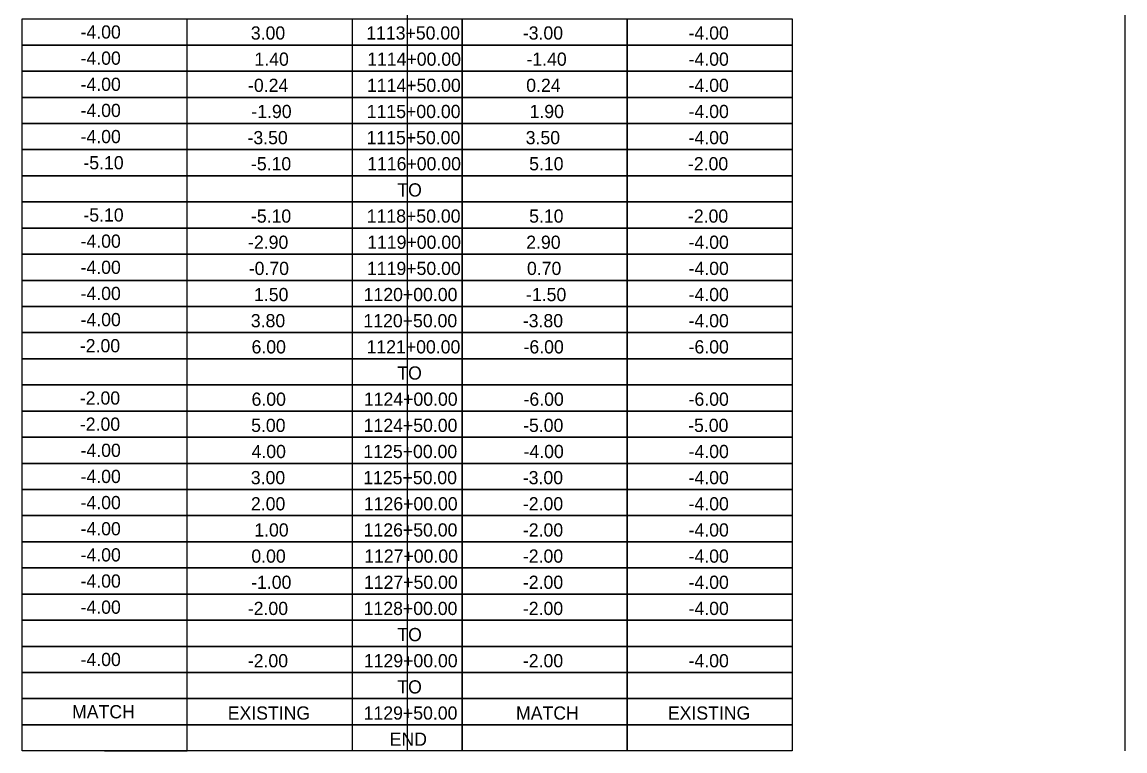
# Model space of a CAD drawing. Extents: x 1026502 to 1027102, y 781811 to 782040.
# Drawn here: x 1026950.62 to 1026990.71, y 781816.1 to 781842.59 of the extents above; entities that cross this region are included whole.
import ezdxf

# ---------------------------------------------------------------- set-up
doc = ezdxf.new("R2010")
doc.units = 0
doc.layers.add('BORDER', color=7, linetype='Continuous')
doc.layers.add('DIMENSIONS', color=7, linetype='Continuous')

msp = doc.modelspace()

# ---------------------------------------------------------------- linework, layer by layer
at = {"layer": 'BORDER'}
for p, q in [((1026964.619, 781922.543), (1026964.619, 781816.098)), ((1026990.71, 781922.543), (1026990.71, 781816.098)), ((1026953.619, 781841.759), (1026950.619, 781841.759)), ((1026953.619, 781841.759), (1026950.619, 781841.759)), ((1026953.619, 781841.759), (1026956.619, 781841.759)), ((1026953.619, 781840.808), (1026950.619, 781840.808)), ((1026953.619, 781840.808), (1026950.619, 781840.808)), ((1026953.619, 781840.808), (1026956.619, 781840.808)), ((1026953.619, 781839.858), (1026950.619, 781839.858)), ((1026953.619, 781839.858), (1026950.619, 781839.858)), ((1026953.619, 781839.858), (1026956.619, 781839.858)), ((1026953.619, 781838.907), (1026950.619, 781838.907)), ((1026953.619, 781838.907), (1026950.619, 781838.907)), ((1026953.619, 781838.907), (1026956.619, 781838.907)), ((1026953.619, 781837.957), (1026950.619, 781837.957)), ((1026953.619, 781837.957), (1026950.619, 781837.957)), ((1026953.619, 781837.957), (1026956.619, 781837.957)), ((1026953.619, 781837.007), (1026950.619, 781837.007)), ((1026953.619, 781837.007), (1026950.619, 781837.007)), ((1026953.619, 781837.007), (1026956.619, 781837.007)), ((1026953.619, 781836.056), (1026950.619, 781836.056)), ((1026953.619, 781836.056), (1026950.619, 781836.056)), ((1026953.619, 781836.056), (1026956.619, 781836.056)), ((1026953.619, 781835.106), (1026950.619, 781835.106)), ((1026953.619, 781835.106), (1026950.619, 781835.106)), ((1026953.619, 781835.106), (1026956.619, 781835.106)), ((1026953.619, 781834.155), (1026950.619, 781834.155)), ((1026953.619, 781834.155), (1026950.619, 781834.155)), ((1026953.619, 781834.155), (1026956.619, 781834.155)), ((1026953.619, 781833.205), (1026950.619, 781833.205)), ((1026953.619, 781833.205), (1026950.619, 781833.205)), ((1026953.619, 781833.205), (1026956.619, 781833.205)), ((1026953.619, 781832.255), (1026950.619, 781832.255)), ((1026953.619, 781832.255), (1026950.619, 781832.255)), ((1026953.619, 781832.255), (1026956.619, 781832.255)), ((1026953.619, 781831.304), (1026950.619, 781831.304)), ((1026953.619, 781831.304), (1026950.619, 781831.304)), ((1026953.619, 781831.304), (1026956.619, 781831.304)), ((1026953.619, 781830.354), (1026950.619, 781830.354)), ((1026953.619, 781830.354), (1026950.619, 781830.354)), ((1026953.619, 781830.354), (1026956.619, 781830.354)), ((1026953.619, 781829.403), (1026950.619, 781829.403)), ((1026953.619, 781829.403), (1026950.619, 781829.403)), ((1026953.619, 781829.403), (1026956.619, 781829.403)), ((1026953.619, 781828.453), (1026950.619, 781828.453)), ((1026953.619, 781828.453), (1026950.619, 781828.453)), ((1026953.619, 781828.453), (1026956.619, 781828.453)), ((1026953.619, 781827.503), (1026950.619, 781827.503)), ((1026953.619, 781827.503), (1026950.619, 781827.503)), ((1026953.619, 781827.503), (1026956.619, 781827.503)), ((1026953.619, 781826.552), (1026950.619, 781826.552)), ((1026953.619, 781826.552), (1026950.619, 781826.552)), ((1026953.619, 781826.552), (1026956.619, 781826.552)), ((1026953.619, 781825.602), (1026950.619, 781825.602)), ((1026953.619, 781825.602), (1026950.619, 781825.602)), ((1026953.619, 781825.602), (1026956.619, 781825.602)), ((1026953.619, 781824.651), (1026950.619, 781824.651)), ((1026953.619, 781824.651), (1026950.619, 781824.651)), ((1026953.619, 781824.651), (1026956.619, 781824.651)), ((1026953.619, 781823.701), (1026950.619, 781823.701)), ((1026953.619, 781823.701), (1026950.619, 781823.701)), ((1026953.619, 781823.701), (1026956.619, 781823.701)), ((1026953.619, 781822.751), (1026950.619, 781822.751)), ((1026953.619, 781822.751), (1026950.619, 781822.751)), ((1026953.619, 781822.751), (1026956.619, 781822.751)), ((1026953.619, 781821.8), (1026950.619, 781821.8)), ((1026953.619, 781821.8), (1026950.619, 781821.8)), ((1026953.619, 781821.8), (1026956.619, 781821.8)), ((1026953.619, 781820.85), (1026950.619, 781820.85)), ((1026953.619, 781820.85), (1026950.619, 781820.85)), ((1026953.619, 781820.85), (1026956.619, 781820.85)), ((1026953.619, 781819.899), (1026950.619, 781819.899)), ((1026953.619, 781819.899), (1026950.619, 781819.899)), ((1026953.619, 781819.899), (1026956.619, 781819.899)), ((1026953.619, 781818.949), (1026950.619, 781818.949)), ((1026953.619, 781818.949), (1026950.619, 781818.949)), ((1026953.619, 781818.949), (1026950.619, 781818.949)), ((1026953.619, 781818.949), (1026956.619, 781818.949)), ((1026953.619, 781818.949), (1026956.619, 781818.949)), ((1026953.619, 781817.999), (1026950.619, 781817.999)), ((1026953.619, 781817.999), (1026950.619, 781817.999)), ((1026953.619, 781817.999), (1026956.619, 781817.999)), ((1026953.619, 781817.048), (1026950.619, 781817.048)), ((1026953.619, 781817.048), (1026950.619, 781817.048)), ((1026953.619, 781817.048), (1026950.619, 781817.048)), ((1026953.619, 781817.048), (1026956.619, 781817.048)), ((1026953.619, 781817.048), (1026956.619, 781817.048)), ((1026953.619, 781816.098), (1026950.619, 781816.098)), ((1026953.619, 781816.098), (1026950.619, 781816.098)), ((1026953.619, 781816.098), (1026956.619, 781816.098))]:
    msp.add_line(p, q, dxfattribs=at)
for points in [[(1026950.619, 781842.709), (1026978.619, 781842.709), (1026978.619, 781841.759), (1026950.619, 781841.759)], [(1026950.619, 781841.759), (1026978.619, 781841.759), (1026978.619, 781840.808), (1026950.619, 781840.808)], [(1026950.619, 781840.808), (1026978.619, 781840.808), (1026978.619, 781839.858), (1026950.619, 781839.858)], [(1026950.619, 781839.858), (1026978.619, 781839.858), (1026978.619, 781838.907), (1026950.619, 781838.907)], [(1026950.619, 781838.907), (1026978.619, 781838.907), (1026978.619, 781837.957), (1026950.619, 781837.957)], [(1026950.619, 781837.957), (1026978.619, 781837.957), (1026978.619, 781837.007), (1026950.619, 781837.007)], [(1026950.619, 781837.007), (1026978.619, 781837.007), (1026978.619, 781836.056), (1026950.619, 781836.056)], [(1026950.619, 781836.056), (1026978.619, 781836.056), (1026978.619, 781835.106), (1026950.619, 781835.106)], [(1026950.619, 781835.106), (1026978.619, 781835.106), (1026978.619, 781834.155), (1026950.619, 781834.155)], [(1026950.619, 781834.155), (1026978.619, 781834.155), (1026978.619, 781833.205), (1026950.619, 781833.205)], [(1026950.619, 781833.205), (1026978.619, 781833.205), (1026978.619, 781832.255), (1026950.619, 781832.255)], [(1026950.619, 781832.255), (1026978.619, 781832.255), (1026978.619, 781831.304), (1026950.619, 781831.304)], [(1026950.619, 781831.304), (1026978.619, 781831.304), (1026978.619, 781830.354), (1026950.619, 781830.354)], [(1026950.619, 781830.354), (1026978.619, 781830.354), (1026978.619, 781829.403), (1026950.619, 781829.403)], [(1026950.619, 781829.403), (1026978.619, 781829.403), (1026978.619, 781828.453), (1026950.619, 781828.453)], [(1026950.619, 781828.453), (1026978.619, 781828.453), (1026978.619, 781827.503), (1026950.619, 781827.503)], [(1026950.619, 781827.503), (1026978.619, 781827.503), (1026978.619, 781826.552), (1026950.619, 781826.552)], [(1026950.619, 781826.552), (1026978.619, 781826.552), (1026978.619, 781825.602), (1026950.619, 781825.602)], [(1026950.619, 781825.602), (1026978.619, 781825.602), (1026978.619, 781824.651), (1026950.619, 781824.651)], [(1026950.619, 781824.651), (1026978.619, 781824.651), (1026978.619, 781823.701), (1026950.619, 781823.701)], [(1026950.619, 781823.701), (1026978.619, 781823.701), (1026978.619, 781822.751), (1026950.619, 781822.751)], [(1026950.619, 781822.751), (1026978.619, 781822.751), (1026978.619, 781821.8), (1026950.619, 781821.8)], [(1026950.619, 781821.8), (1026978.619, 781821.8), (1026978.619, 781820.85), (1026950.619, 781820.85)], [(1026950.619, 781820.85), (1026978.619, 781820.85), (1026978.619, 781819.899), (1026950.619, 781819.899)], [(1026950.619, 781819.899), (1026978.619, 781819.899), (1026978.619, 781818.949), (1026950.619, 781818.949)], [(1026950.619, 781818.949), (1026978.619, 781818.949), (1026978.619, 781817.999), (1026950.619, 781817.999)], [(1026950.619, 781817.999), (1026978.619, 781817.999), (1026978.619, 781817.048), (1026950.619, 781817.048)], [(1026950.619, 781817.048), (1026978.619, 781817.048), (1026978.619, 781816.098), (1026950.619, 781816.098)]]:
    msp.add_lwpolyline(points, close=True, dxfattribs=at)
for points in [[(1026962.619, 781842.709), (1026962.619, 781841.759), (1026956.619, 781841.759), (1026956.619, 781842.709)], [(1026966.619, 781842.709), (1026966.619, 781841.759), (1026962.619, 781841.759)], [(1026972.619, 781842.709), (1026972.619, 781841.759), (1026966.619, 781841.759), (1026966.619, 781842.709)], [(1026978.619, 781842.709), (1026978.619, 781841.759), (1026972.619, 781841.759), (1026972.619, 781842.709)], [(1026962.619, 781841.759), (1026962.619, 781840.808), (1026956.619, 781840.808), (1026956.619, 781841.759)], [(1026966.619, 781841.759), (1026966.619, 781840.808), (1026962.619, 781840.808)], [(1026972.619, 781841.759), (1026972.619, 781840.808), (1026966.619, 781840.808), (1026966.619, 781841.759)], [(1026978.619, 781841.759), (1026978.619, 781840.808), (1026972.619, 781840.808), (1026972.619, 781841.759)], [(1026962.619, 781840.808), (1026962.619, 781839.858), (1026956.619, 781839.858), (1026956.619, 781840.808)], [(1026966.619, 781840.808), (1026966.619, 781839.858), (1026962.619, 781839.858)], [(1026972.619, 781840.808), (1026972.619, 781839.858), (1026966.619, 781839.858), (1026966.619, 781840.808)], [(1026978.619, 781840.808), (1026978.619, 781839.858), (1026972.619, 781839.858), (1026972.619, 781840.808)], [(1026962.619, 781839.858), (1026962.619, 781838.907), (1026956.619, 781838.907), (1026956.619, 781839.858)], [(1026966.619, 781839.858), (1026966.619, 781838.907), (1026962.619, 781838.907)], [(1026972.619, 781839.858), (1026972.619, 781838.907), (1026966.619, 781838.907), (1026966.619, 781839.858)], [(1026978.619, 781839.858), (1026978.619, 781838.907), (1026972.619, 781838.907), (1026972.619, 781839.858)], [(1026962.619, 781838.907), (1026962.619, 781837.957), (1026956.619, 781837.957), (1026956.619, 781838.907)], [(1026966.619, 781838.907), (1026966.619, 781837.957), (1026962.619, 781837.957)], [(1026972.619, 781838.907), (1026972.619, 781837.957), (1026966.619, 781837.957), (1026966.619, 781838.907)], [(1026978.619, 781838.907), (1026978.619, 781837.957), (1026972.619, 781837.957), (1026972.619, 781838.907)], [(1026962.619, 781837.957), (1026962.619, 781837.007), (1026956.619, 781837.007), (1026956.619, 781837.957)], [(1026966.619, 781837.957), (1026966.619, 781837.007), (1026962.619, 781837.007)], [(1026972.619, 781837.957), (1026972.619, 781837.007), (1026966.619, 781837.007), (1026966.619, 781837.957)], [(1026978.619, 781837.957), (1026978.619, 781837.007), (1026972.619, 781837.007), (1026972.619, 781837.957)], [(1026962.619, 781837.007), (1026962.619, 781836.056), (1026956.619, 781836.056), (1026956.619, 781837.007)], [(1026966.619, 781837.007), (1026966.619, 781836.056), (1026962.619, 781836.056)], [(1026972.619, 781837.007), (1026972.619, 781836.056), (1026966.619, 781836.056), (1026966.619, 781837.007)], [(1026978.619, 781837.007), (1026978.619, 781836.056), (1026972.619, 781836.056), (1026972.619, 781837.007)], [(1026962.619, 781836.056), (1026962.619, 781835.106), (1026956.619, 781835.106), (1026956.619, 781836.056)], [(1026966.619, 781836.056), (1026966.619, 781835.106), (1026962.619, 781835.106)], [(1026972.619, 781836.056), (1026972.619, 781835.106), (1026966.619, 781835.106), (1026966.619, 781836.056)], [(1026978.619, 781836.056), (1026978.619, 781835.106), (1026972.619, 781835.106), (1026972.619, 781836.056)], [(1026962.619, 781835.106), (1026962.619, 781834.155), (1026956.619, 781834.155), (1026956.619, 781835.106)], [(1026966.619, 781835.106), (1026966.619, 781834.155), (1026962.619, 781834.155)], [(1026972.619, 781835.106), (1026972.619, 781834.155), (1026966.619, 781834.155), (1026966.619, 781835.106)], [(1026978.619, 781835.106), (1026978.619, 781834.155), (1026972.619, 781834.155), (1026972.619, 781835.106)], [(1026962.619, 781834.155), (1026962.619, 781833.205), (1026956.619, 781833.205), (1026956.619, 781834.155)], [(1026966.619, 781834.155), (1026966.619, 781833.205), (1026962.619, 781833.205)], [(1026972.619, 781834.155), (1026972.619, 781833.205), (1026966.619, 781833.205), (1026966.619, 781834.155)], [(1026978.619, 781834.155), (1026978.619, 781833.205), (1026972.619, 781833.205), (1026972.619, 781834.155)], [(1026962.619, 781833.205), (1026962.619, 781832.255), (1026956.619, 781832.255), (1026956.619, 781833.205)], [(1026966.619, 781833.205), (1026966.619, 781832.255), (1026962.619, 781832.255)], [(1026972.619, 781833.205), (1026972.619, 781832.255), (1026966.619, 781832.255), (1026966.619, 781833.205)], [(1026978.619, 781833.205), (1026978.619, 781832.255), (1026972.619, 781832.255), (1026972.619, 781833.205)], [(1026962.619, 781832.255), (1026962.619, 781831.304), (1026956.619, 781831.304), (1026956.619, 781832.255)], [(1026966.619, 781832.255), (1026966.619, 781831.304), (1026962.619, 781831.304)], [(1026972.619, 781832.255), (1026972.619, 781831.304), (1026966.619, 781831.304), (1026966.619, 781832.255)], [(1026978.619, 781832.255), (1026978.619, 781831.304), (1026972.619, 781831.304), (1026972.619, 781832.255)], [(1026962.619, 781831.304), (1026962.619, 781830.354), (1026956.619, 781830.354), (1026956.619, 781831.304)], [(1026966.619, 781831.304), (1026966.619, 781830.354), (1026962.619, 781830.354)], [(1026972.619, 781831.304), (1026972.619, 781830.354), (1026966.619, 781830.354), (1026966.619, 781831.304)], [(1026978.619, 781831.304), (1026978.619, 781830.354), (1026972.619, 781830.354), (1026972.619, 781831.304)], [(1026962.619, 781830.354), (1026962.619, 781829.403), (1026956.619, 781829.403), (1026956.619, 781830.354)], [(1026966.619, 781830.354), (1026966.619, 781829.403), (1026962.619, 781829.403)], [(1026972.619, 781830.354), (1026972.619, 781829.403), (1026966.619, 781829.403), (1026966.619, 781830.354)], [(1026978.619, 781830.354), (1026978.619, 781829.403), (1026972.619, 781829.403), (1026972.619, 781830.354)], [(1026962.619, 781829.403), (1026962.619, 781828.453), (1026956.619, 781828.453), (1026956.619, 781829.403)], [(1026966.619, 781829.403), (1026966.619, 781828.453), (1026962.619, 781828.453)], [(1026972.619, 781829.403), (1026972.619, 781828.453), (1026966.619, 781828.453), (1026966.619, 781829.403)], [(1026978.619, 781829.403), (1026978.619, 781828.453), (1026972.619, 781828.453), (1026972.619, 781829.403)], [(1026962.619, 781828.453), (1026962.619, 781827.503), (1026956.619, 781827.503), (1026956.619, 781828.453)], [(1026966.619, 781828.453), (1026966.619, 781827.503), (1026962.619, 781827.503)], [(1026972.619, 781828.453), (1026972.619, 781827.503), (1026966.619, 781827.503), (1026966.619, 781828.453)], [(1026978.619, 781828.453), (1026978.619, 781827.503), (1026972.619, 781827.503), (1026972.619, 781828.453)], [(1026962.619, 781827.503), (1026962.619, 781826.552), (1026956.619, 781826.552), (1026956.619, 781827.503)], [(1026966.619, 781827.503), (1026966.619, 781826.552), (1026962.619, 781826.552)], [(1026972.619, 781827.503), (1026972.619, 781826.552), (1026966.619, 781826.552), (1026966.619, 781827.503)], [(1026978.619, 781827.503), (1026978.619, 781826.552), (1026972.619, 781826.552), (1026972.619, 781827.503)], [(1026962.619, 781826.552), (1026962.619, 781825.602), (1026956.619, 781825.602), (1026956.619, 781826.552)], [(1026966.619, 781826.552), (1026966.619, 781825.602), (1026962.619, 781825.602)], [(1026972.619, 781826.552), (1026972.619, 781825.602), (1026966.619, 781825.602), (1026966.619, 781826.552)], [(1026978.619, 781826.552), (1026978.619, 781825.602), (1026972.619, 781825.602), (1026972.619, 781826.552)], [(1026962.619, 781825.602), (1026962.619, 781824.651), (1026956.619, 781824.651), (1026956.619, 781825.602)], [(1026966.619, 781825.602), (1026966.619, 781824.651), (1026962.619, 781824.651)], [(1026972.619, 781825.602), (1026972.619, 781824.651), (1026966.619, 781824.651), (1026966.619, 781825.602)], [(1026978.619, 781825.602), (1026978.619, 781824.651), (1026972.619, 781824.651), (1026972.619, 781825.602)], [(1026962.619, 781824.651), (1026962.619, 781823.701), (1026956.619, 781823.701), (1026956.619, 781824.651)], [(1026966.619, 781824.651), (1026966.619, 781823.701), (1026962.619, 781823.701)], [(1026972.619, 781824.651), (1026972.619, 781823.701), (1026966.619, 781823.701), (1026966.619, 781824.651)], [(1026978.619, 781824.651), (1026978.619, 781823.701), (1026972.619, 781823.701), (1026972.619, 781824.651)], [(1026962.619, 781823.701), (1026962.619, 781822.751), (1026956.619, 781822.751), (1026956.619, 781823.701)], [(1026966.619, 781823.701), (1026966.619, 781822.751), (1026962.619, 781822.751)], [(1026972.619, 781823.701), (1026972.619, 781822.751), (1026966.619, 781822.751), (1026966.619, 781823.701)], [(1026978.619, 781823.701), (1026978.619, 781822.751), (1026972.619, 781822.751), (1026972.619, 781823.701)], [(1026962.619, 781822.751), (1026962.619, 781821.8), (1026956.619, 781821.8), (1026956.619, 781822.751)], [(1026966.619, 781822.751), (1026966.619, 781821.8), (1026962.619, 781821.8)], [(1026972.619, 781822.751), (1026972.619, 781821.8), (1026966.619, 781821.8), (1026966.619, 781822.751)], [(1026978.619, 781822.751), (1026978.619, 781821.8), (1026972.619, 781821.8), (1026972.619, 781822.751)], [(1026962.619, 781821.8), (1026962.619, 781820.85), (1026956.619, 781820.85), (1026956.619, 781821.8)], [(1026966.619, 781821.8), (1026966.619, 781820.85), (1026962.619, 781820.85)], [(1026972.619, 781821.8), (1026972.619, 781820.85), (1026966.619, 781820.85), (1026966.619, 781821.8)], [(1026978.619, 781821.8), (1026978.619, 781820.85), (1026972.619, 781820.85), (1026972.619, 781821.8)], [(1026962.619, 781820.85), (1026962.619, 781819.899), (1026956.619, 781819.899), (1026956.619, 781820.85)], [(1026966.619, 781820.85), (1026966.619, 781819.899), (1026962.619, 781819.899)], [(1026972.619, 781820.85), (1026972.619, 781819.899), (1026966.619, 781819.899), (1026966.619, 781820.85)], [(1026978.619, 781820.85), (1026978.619, 781819.899), (1026972.619, 781819.899), (1026972.619, 781820.85)], [(1026962.619, 781819.899), (1026962.619, 781818.949), (1026956.619, 781818.949), (1026956.619, 781819.899)], [(1026966.619, 781819.899), (1026966.619, 781818.949), (1026962.619, 781818.949)], [(1026972.619, 781819.899), (1026972.619, 781818.949), (1026966.619, 781818.949), (1026966.619, 781819.899)], [(1026978.619, 781819.899), (1026978.619, 781818.949), (1026972.619, 781818.949), (1026972.619, 781819.899)], [(1026962.619, 781818.949), (1026962.619, 781817.999), (1026956.619, 781817.999), (1026956.619, 781818.949)], [(1026966.619, 781818.949), (1026966.619, 781817.999), (1026962.619, 781817.999)], [(1026972.619, 781818.949), (1026972.619, 781817.999), (1026966.619, 781817.999), (1026966.619, 781818.949)], [(1026978.619, 781818.949), (1026978.619, 781817.999), (1026972.619, 781817.999), (1026972.619, 781818.949)], [(1026962.619, 781817.999), (1026962.619, 781817.048), (1026956.619, 781817.048), (1026956.619, 781817.999)], [(1026966.619, 781817.999), (1026966.619, 781817.048), (1026962.619, 781817.048)], [(1026972.619, 781817.999), (1026972.619, 781817.048), (1026966.619, 781817.048), (1026966.619, 781817.999)], [(1026978.619, 781817.999), (1026978.619, 781817.048), (1026972.619, 781817.048), (1026972.619, 781817.999)], [(1026962.619, 781817.048), (1026962.619, 781816.098), (1026956.619, 781816.098), (1026956.619, 781817.048)], [(1026966.619, 781817.048), (1026966.619, 781816.098), (1026962.619, 781816.098)], [(1026972.619, 781817.048), (1026972.619, 781816.098), (1026966.619, 781816.098), (1026966.619, 781817.048)], [(1026978.619, 781817.048), (1026978.619, 781816.098), (1026972.619, 781816.098), (1026972.619, 781817.048)]]:
    msp.add_lwpolyline(points, dxfattribs=at)

# ---------------------------------------------------------------- texts
at = {"layer": 'DIMENSIONS'}
for s, p in [('-4.00', (1026952.745, 781841.994)), ('3.00', (1026958.935, 781841.958)), ('1113+50.00', (1026963.13, 781841.958)), ('-3.00', (1026968.822, 781841.958)), ('-4.00', (1026974.848, 781841.958)), ('-4.00', (1026952.745, 781841.043)), ('1.40', (1026959.067, 781841.007)), ('1114+00.00', (1026963.164, 781841.007)), ('-1.40', (1026968.954, 781841.007)), ('-4.00', (1026974.848, 781841.007)), ('-4.00', (1026952.745, 781840.093)), ('-0.24', (1026958.833, 781840.056)), ('1114+50.00', (1026963.157, 781840.056)), ('0.24', (1026968.946, 781840.056)), ('-4.00', (1026974.848, 781840.056)), ('-4.00', (1026952.745, 781839.143)), ('-1.90', (1026958.954, 781839.105)), ('1115+00.00', (1026963.149, 781839.105)), ('1.90', (1026969.067, 781839.105)), ('-4.00', (1026974.848, 781839.105)), ('-4.00', (1026952.745, 781838.192)), ('-3.50', (1026958.814, 781838.154)), ('1115+50.00', (1026963.142, 781838.154)), ('3.50', (1026968.927, 781838.154)), ('-4.00', (1026974.848, 781838.154)), ('-5.10', (1026952.848, 781837.242)), ('-5.10', (1026958.939, 781837.204)), ('1116+00.00', (1026963.164, 781837.204)), ('5.10', (1026969.052, 781837.204)), ('-2.00', (1026974.825, 781837.204)), ('TO', (1026964.26, 781836.253)), ('-5.10', (1026952.848, 781835.341)), ('-5.10', (1026958.939, 781835.302)), ('1118+50.00', (1026963.149, 781835.302)), ('5.10', (1026969.052, 781835.302)), ('-2.00', (1026974.825, 781835.302)), ('-4.00', (1026952.745, 781834.391)), ('-2.90', (1026958.833, 781834.351)), ('1119+00.00', (1026963.164, 781834.351)), ('2.90', (1026968.946, 781834.351)), ('-4.00', (1026974.848, 781834.351)), ('-4.00', (1026952.745, 781833.44)), ('-0.70', (1026958.859, 781833.4)), ('1119+50.00', (1026963.157, 781833.4)), ('0.70', (1026968.973, 781833.4)), ('-4.00', (1026974.848, 781833.4)), ('-4.00', (1026952.745, 781832.49)), ('1.50', (1026959.052, 781832.449)), ('1120+00.00', (1026963.036, 781832.449)), ('-1.50', (1026968.939, 781832.449)), ('-4.00', (1026974.848, 781832.449)), ('-4.00', (1026952.745, 781831.539)), ('3.80', (1026958.935, 781831.499)), ('1120+50.00', (1026963.028, 781831.499)), ('-3.80', (1026968.822, 781831.499)), ('-4.00', (1026974.848, 781831.499)), ('-2.00', (1026952.72, 781830.589)), ('6.00', (1026958.961, 781830.548)), ('1121+00.00', (1026963.142, 781830.548)), ('-6.00', (1026968.848, 781830.548)), ('-6.00', (1026974.848, 781830.548)), ('TO', (1026964.26, 781829.597)), ('-2.00', (1026952.72, 781828.688)), ('6.00', (1026958.961, 781828.646)), ('1124+00.00', (1026963.043, 781828.646)), ('-6.00', (1026968.848, 781828.646)), ('-6.00', (1026974.848, 781828.646)), ('-2.00', (1026952.72, 781827.738)), ('5.00', (1026958.946, 781827.695)), ('1124+50.00', (1026963.036, 781827.695)), ('-5.00', (1026968.833, 781827.695)), ('-5.00', (1026974.833, 781827.695)), ('-4.00', (1026952.745, 781826.787)), ('4.00', (1026958.961, 781826.744)), ('1125+00.00', (1026963.028, 781826.744)), ('-4.00', (1026968.848, 781826.744)), ('-4.00', (1026974.848, 781826.744)), ('-4.00', (1026952.745, 781825.837)), ('3.00', (1026958.935, 781825.794)), ('1125+50.00', (1026963.021, 781825.794)), ('-3.00', (1026968.822, 781825.794)), ('-4.00', (1026974.848, 781825.794)), ('-4.00', (1026952.745, 781824.887)), ('2.00', (1026958.939, 781824.843)), ('1126+00.00', (1026963.043, 781824.843)), ('-2.00', (1026968.825, 781824.843)), ('-4.00', (1026974.848, 781824.843)), ('-4.00', (1026952.745, 781823.936)), ('1.00', (1026959.06, 781823.892)), ('1126+50.00', (1026963.036, 781823.892)), ('-2.00', (1026968.825, 781823.892)), ('-4.00', (1026974.848, 781823.892)), ('-4.00', (1026952.745, 781822.986)), ('0.00', (1026958.954, 781822.941)), ('1127+00.00', (1026963.055, 781822.941)), ('-2.00', (1026968.825, 781822.941)), ('-4.00', (1026974.848, 781822.941)), ('-4.00', (1026952.745, 781822.035)), ('-1.00', (1026958.946, 781821.99)), ('1127+50.00', (1026963.047, 781821.99)), ('-2.00', (1026968.825, 781821.99)), ('-4.00', (1026974.848, 781821.99)), ('-4.00', (1026952.745, 781821.085)), ('-2.00', (1026958.825, 781821.039)), ('1128+00.00', (1026963.036, 781821.039)), ('-2.00', (1026968.825, 781821.039)), ('-4.00', (1026974.848, 781821.039)), ('TO', (1026964.26, 781820.089)), ('-4.00', (1026952.745, 781819.184)), ('-2.00', (1026958.825, 781819.138)), ('1129+00.00', (1026963.043, 781819.138)), ('-2.00', (1026968.825, 781819.138)), ('-4.00', (1026974.848, 781819.138)), ('TO', (1026964.26, 781818.187)), ('MATCH', (1026952.436, 781817.283)), ('EXISTING', (1026958.095, 781817.236)), ('1129+50.00', (1026963.036, 781817.236)), ('MATCH', (1026968.575, 781817.236)), ('EXISTING', (1026974.095, 781817.236)), ('END', (1026963.983, 781816.285))]:
    msp.add_text(s, height=0.48, dxfattribs=at).set_placement(p)

doc.saveas('drawing.dxf')
